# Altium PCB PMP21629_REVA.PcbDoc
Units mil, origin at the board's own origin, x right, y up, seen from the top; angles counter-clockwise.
Board outline 2050 x 1500 mil, 2 copper layers (Top Layer, Bottom Layer), stack 62 mil thick; 56 components, 27 nets, 156 pads, 15 vias.
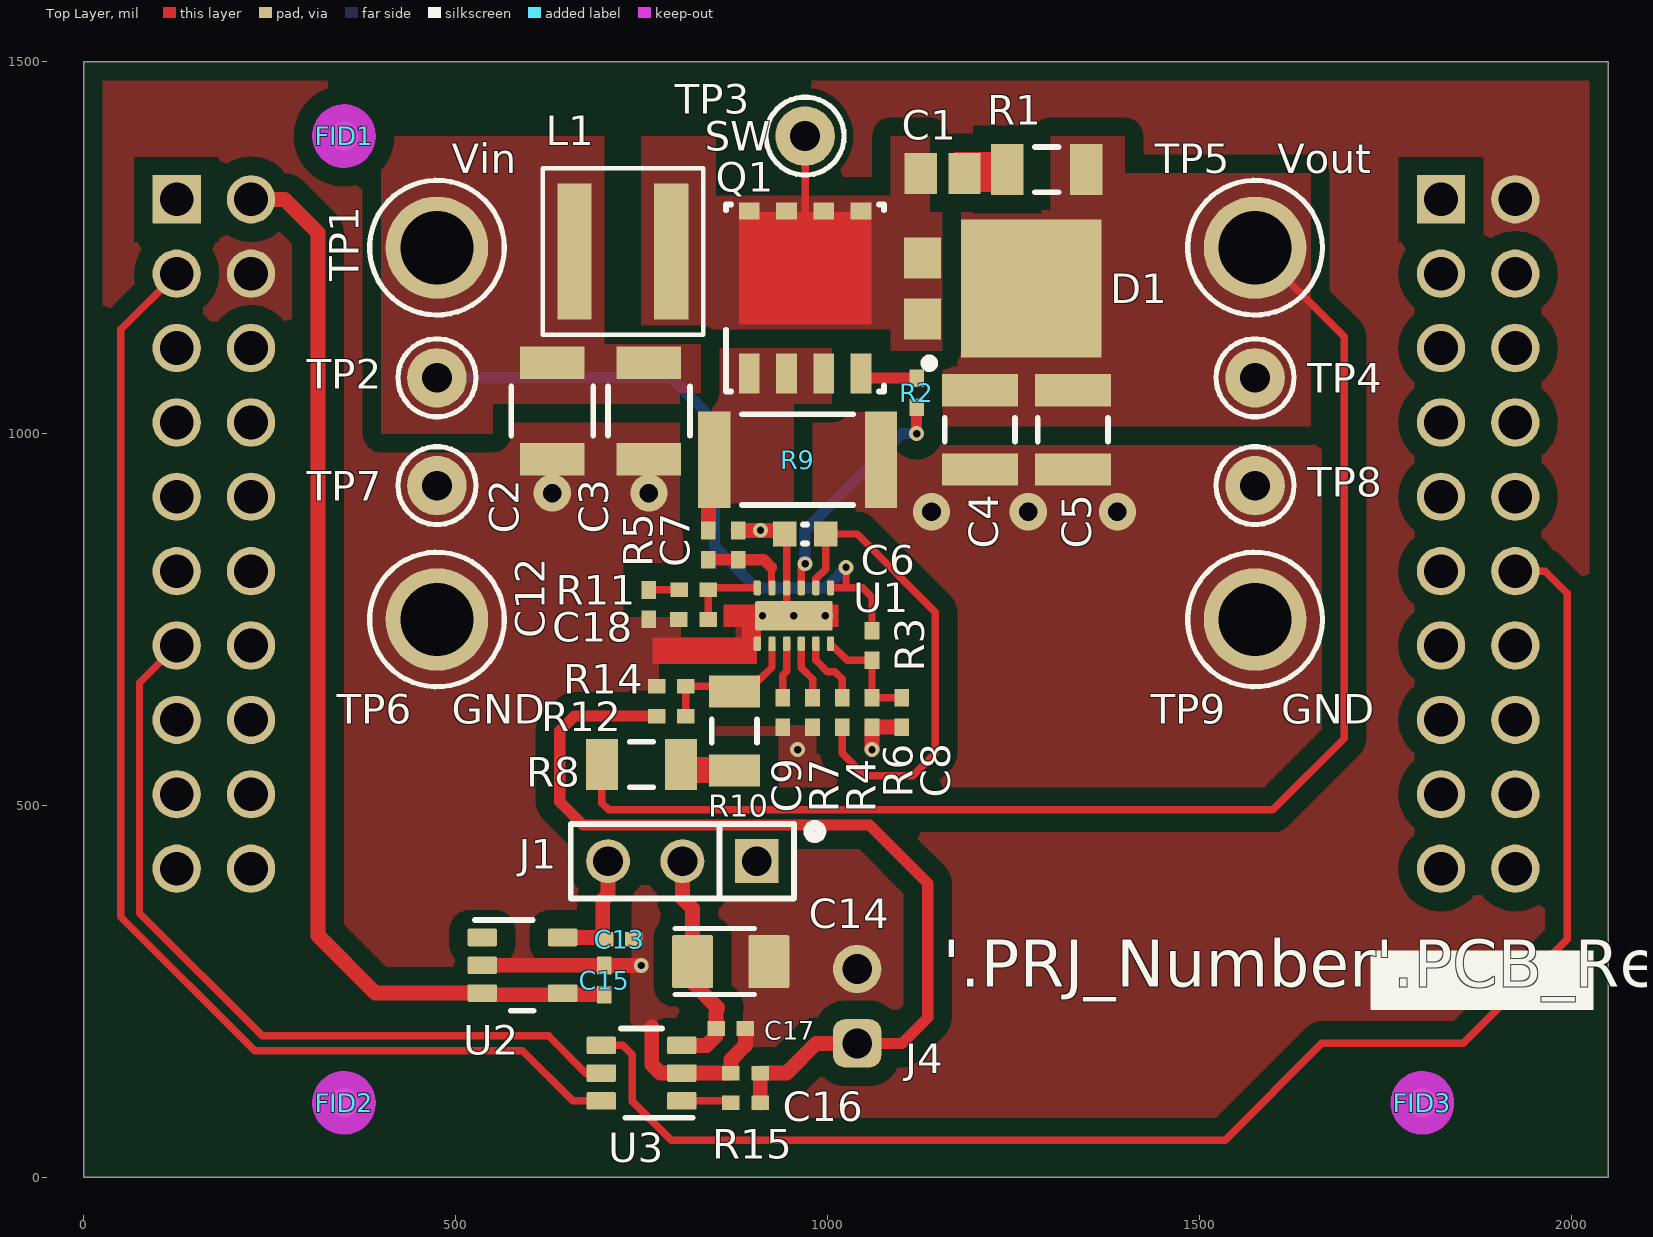
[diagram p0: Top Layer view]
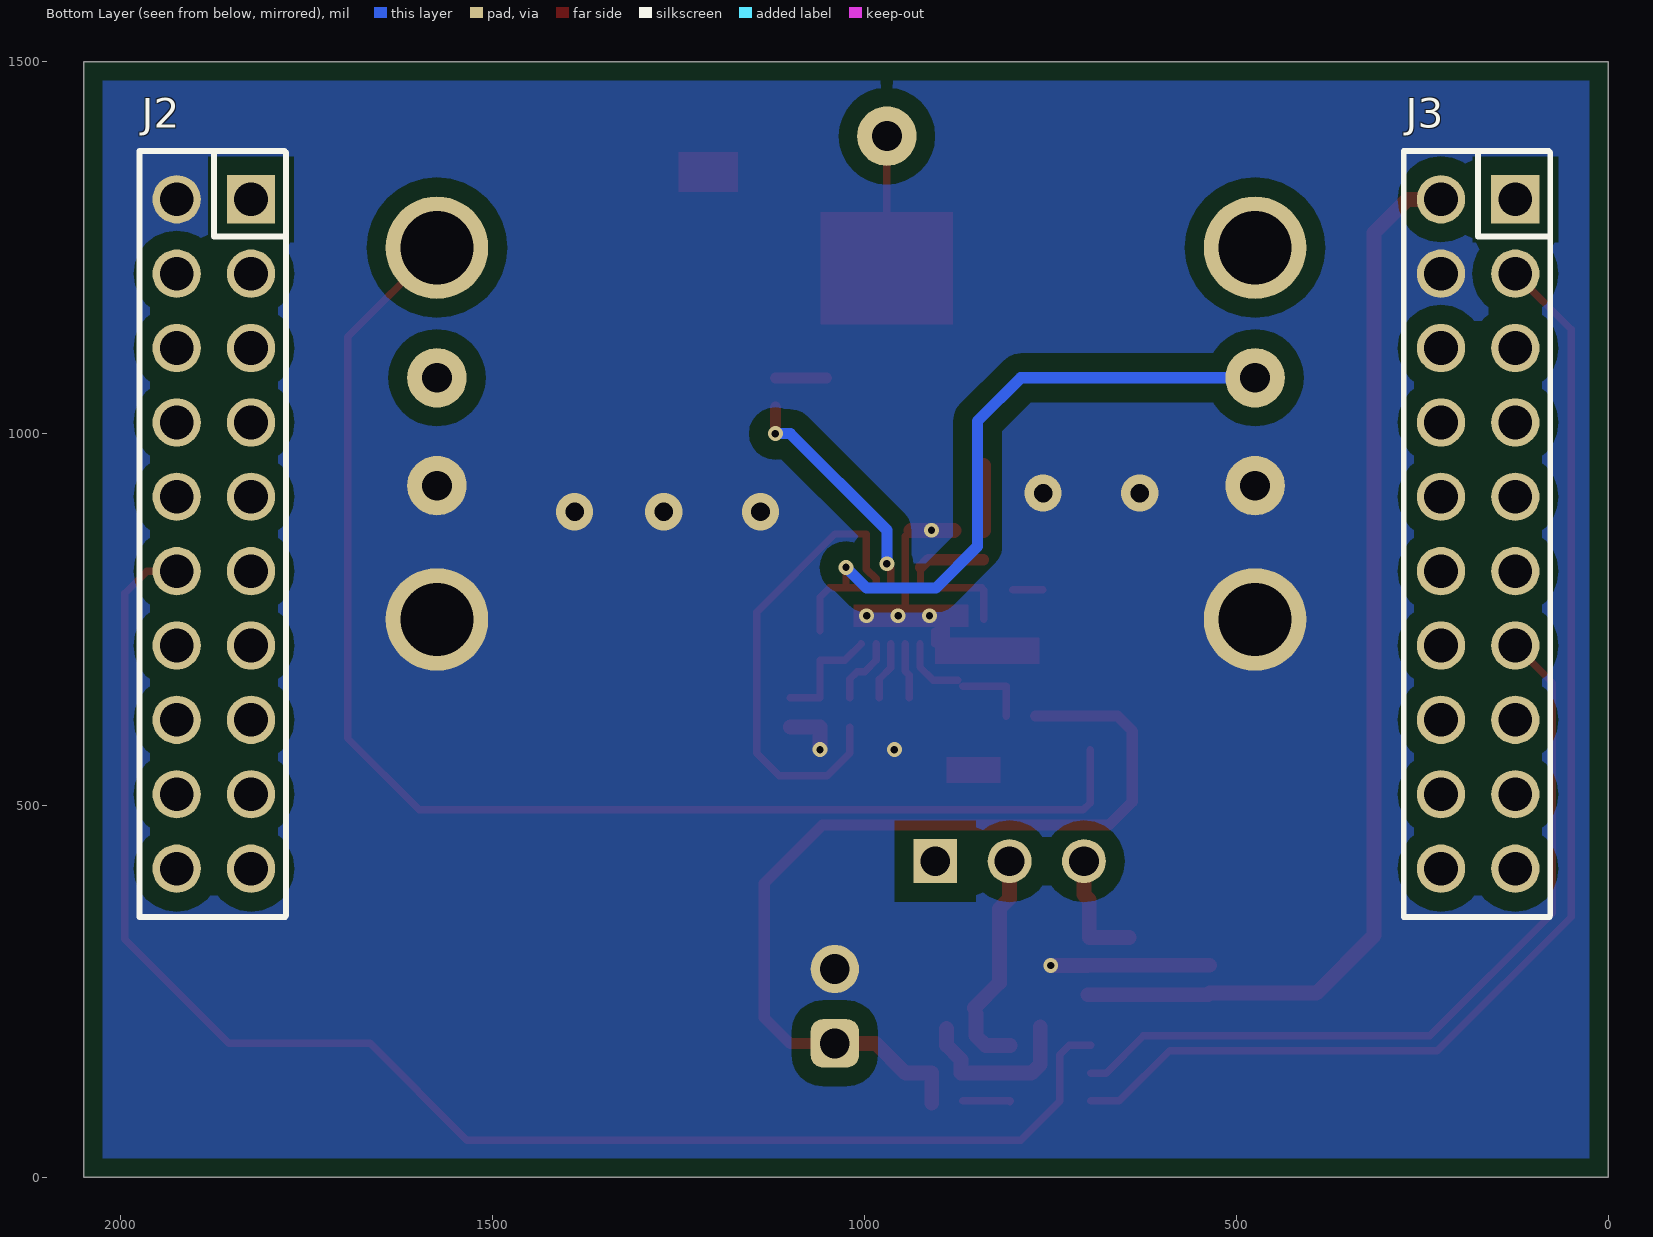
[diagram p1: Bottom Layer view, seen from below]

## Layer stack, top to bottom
Top Solder: solder mask 0.4, Solder Resist, Dk 3.5
Top Layer: signal copper 1.4
Dielectric1: core 59.2, FR-4, Dk 4.8
Bottom Layer: signal copper 1.4
Bottom Solder: solder mask 0.4, Solder Resist, Dk 3.5

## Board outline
0,0 2050,0 2050,1500 0,1500

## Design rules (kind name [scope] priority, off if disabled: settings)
AcuteAngle [All] p1: minimum=4.50000000000000E+0001 checktracksonly=FALSE
AssemblyTestPointUsage [All] p1: valid=2
BoardOutlineClearance BoardOutlineClearance_MountingHoles [OnCopper and InComponentClass('Mounting Holes')] p1: gap=40 ignorepadtopadclearanceinfootprint=FALSE
BoardOutlineClearance BoardOutlineClearance_Poly [OnCopper and IsPoly] p2: gap=25 ignorepadtopadclearanceinfootprint=FALSE
BoardOutlineClearance [OnCopper and Not InComponentClass('Logo') and not InComponentClass('FiducialMark') and not InRegion(1000,500,4000,800) and not InPoly] p3: gap=40 ignorepadtopadclearanceinfootprint=FALSE
Clearance Clearance_Keepouts [((IsTrack Or IsArc) And Not InPoly) And IsFree and IsKeepOut vs ((IsTrack Or IsArc) And Not InPoly) And IsFree and IsKeepOut] p1: gap=0 ignorepadtopadclearanceinfootprint=FALSE
Clearance Clearance_Poly [InPolygon] p2: gap=25 ignorepadtopadclearanceinfootprint=FALSE except(0: Arc-Hole Track-Hole SMDPad-Hole THPad-Hole Via-Hole Fill-Hole Poly-Hole Region-Hole Text-Hole)
Clearance Clearance_FiducialMark [IsKeepOut and InComponentClass('FiducialMark') vs IsPad and InComponentClass('FiducialMark')] p3: gap=0 ignorepadtopadclearanceinfootprint=FALSE
Clearance [All] p4: gap=7.87 ignorepadtopadclearanceinfootprint=FALSE except(0: Arc-Hole Track-Hole SMDPad-Hole THPad-Hole Via-Hole Fill-Hole Poly-Hole Region-Hole Text-Hole)
ComponentClearance ComponentClearance_MountingHoles_FiducialMarks [InComponentClass('Mounting Holes') vs InComponentClass('FiducialMark')] p1: gap=50 collisioncheckmode=3 verticalgap=10 showdistances=FALSE
ComponentClearance ComponentClearance_Shunt [InComponentClass('Header') vs InComponentClass('Shunt')] p2: gap=0 collisioncheckmode=3 verticalgap=0 showdistances=FALSE
ComponentClearance ComponentClearance_Logo [InComponentClass('Logo')] p3: gap=50 collisioncheckmode=3 verticalgap=10 showdistances=FALSE
ComponentClearance ComponentClearance_ScrewToNut [(HasFootprint('NY PMS 440 0025 PH')) vs (HasFootprint('Keystone_1902C'))] p4: gap=5 collisioncheckmode=3 verticalgap=10 showdistances=FALSE
ComponentClearance ComponentClearance_MountingHoles [InComponentClass('Mounting Holes')] p5: gap=250 collisioncheckmode=3 verticalgap=100000 showdistances=FALSE
ComponentClearance ComponentClearance_SmallPassives [HasFootprint('0201*') or HasFootprint('0402*') or HasFootprint('0508') or HasFootprint('0603*') or HasFootprint('0612') or HasFootprint('0805*') or HasFootprint('0815*') or HasFootprint('0830*') or HasFootprint('1206*') or HasFootprint('1210*') or HasFootprint('1808*') or HasFootprint('1812*') or HasFootprint('1825*') or HasFootprint('2010*') or HasFootprint('2220*') or HasFootprint('2225*') or HasFootprint('2512*') or HasFootprint('2728*') or HasFootprint('3518*') vs HasFootprint('0201*') or HasFootprint('0402*') or HasFootprint('0508') or HasFootprint('0603*') or HasFootprint('0612') or HasFootprint('0805*') or HasFootprint('0815*') or HasFootprint('0830*') or HasFootprint('1206*') or HasFootprint('1210*') or HasFootprint('1808*') or HasFootprint('1812*') or HasFootprint('1825*') or HasFootprint('2010*') or HasFootprint('2220*') or HasFootprint('2225*') or HasFootprint('2512*') or HasFootprint('2728*') or HasFootprint('3518*')] p6: gap=14.96 collisioncheckmode=3 verticalgap=10 showdistances=FALSE
ComponentClearance ComponentClearance_THtoSMT [IsThruComponent vs IsSMTComponent] p7: gap=40 collisioncheckmode=3 verticalgap=30 showdistances=FALSE
ComponentClearance ComponentClearance_THtoTH [IsThruComponent vs IsThruComponent] p8: gap=30 collisioncheckmode=3 verticalgap=30 showdistances=FALSE
ComponentClearance [All] p9: gap=30 collisioncheckmode=3 verticalgap=10 showdistances=FALSE
DiffPairsRouting [All] p1: maxlimit=100 minlimit=10 mostfreqgap=10 toplayer_minwidth=15 toplayer_maxwidth=15 toplayer_prefwidth=15 bottomlayer_minwidth=15 bottomlayer_maxwidth=15 bottomlayer_prefwidth=15 maxuncoupledlength=1000
FabricationTestPointUsage TestPointUsage [All] p1: valid=2 allowmultiple=FALSE
FabricationTestpoint Testpoint [All] p1: side=3 testpointundercomponent=TRUE minsize=40 maxsize=100 preferedsize=60 minholesize=0 maxholesize=40 preferedholesize=32 testpointgrid=1 allowsidetop=TRUE allowsidebottom=TRUE usegrid=TRUE gridtolerance=0.01
FanoutControl Fanout_LCC [IsLCC] p1: bgadir=Out bgaviamode=Centered fanoutstyle=Auto fanoutdirection=Alternating viagrid=1 // Fanout_LCC (Default Rule)
FanoutControl Fanout_BGA [IsBGA] p2: bgadir=Out bgaviamode=Centered fanoutstyle=Auto fanoutdirection=Alternating viagrid=1 // Fanout_BGA (Default Rule)
FanoutControl Fanout_Default [All] p4: bgadir=Out bgaviamode=Centered fanoutstyle=Auto fanoutdirection=Alternating viagrid=1 // Fanout_Default (Default Rule)
FanoutControl Fanout_Small [(CompPinCount < 5)] p5: bgadir=Out bgaviamode=Centered fanoutstyle=Auto fanoutdirection=OutThenIn viagrid=1 // Fanout_Small (Default Rule)
HoleSize [All] p1: absolutevalues=TRUE maxlimit=251 minlimit=7.87 maxpercent=80.000 minpercent=20.000
MinimumAnnularRing MinimumAnnularRing_ThermalPadVias [IsVia and InAnyComponent] p1: minimumring=5.91
MinimumAnnularRing [All] p2: minimumring=8
MinimumSolderMaskSliver MinimumSolderMaskSliver_Logo [InComponentClass('Logo') vs InComponentClass('Logo')] p1: minsoldermaskwidth=0.7
MinimumSolderMaskSliver [All] p2: minsoldermaskwidth=3.94
PlaneConnect [All] p1: planeconnectstyle=Direct reliefexpansion=10 reliefentries=4 reliefconductorwidth=10 reliefairgap=10
PolygonConnect [All] p1: connectstyle=Direct reliefconductorwidth=10 reliefentries=4 polygonreliefangle="90 Angle" airgapwidth=10
RoutingVias ThermalPadVias [IsVia and InAnyComponent] p1: holewidth=7.87 width=19.68 viastyle="Through Hole" minholewidth=7.87 minwidth=19.68 maxholewidth=12.99 maxwidth=23.62
RoutingVias [All] p2: holewidth=16 width=34 viastyle="Through Hole" minholewidth=7.87 minwidth=26 maxholewidth=40 maxwidth=65
SilkToBoardRegionClearance [Not ((IsComment or IsDesignator) And (Hide <> 'False')) and not InRegion(1000,500,4000,800)] p1:
SilkToSilkClearance SilkToSilkClearance_Pb-FreeLogo [(HasFootprint('Pb-Free_Overlay_Medium') OR HasFootprint('Pb-Free_Overlay_Small')) vs (HasFootprint('Pb-Free_Overlay_Medium') OR HasFootprint('Pb-Free_Overlay_Small'))] p1: silktosilkclearance=0
SilkToSilkClearance [All] p2: silktosilkclearance=4
SilkToSolderMaskClearance SilkToComponentPadClearance [(IsPad or IsFill or IsRegion) and InAnycomponent] p1: minsilkscreentomaskgap=5 clearancetoexposedcopper=TRUE
SilkToSolderMaskClearance "Silk to Solder Mask Opening" [All] p2: minsilkscreentomaskgap=4 clearancetoexposedcopper=FALSE
SolderMaskExpansion [All] p1: expansion=1.97
Width [All] p1: maxlimit=100 minlimit=6 preferedwidth=10 checkconnectedcopper=TRUE
15 further rules are at their usual default settings.

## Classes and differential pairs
component class AssemblyNote: ZZ1 ZZ2 ZZ3 ZZ4
component class FiducialMark: FID1 FID2 FID3
component class PMP21629_REVA_Hardware: FID1 FID2 FID3 ZZ1 ZZ2 ZZ3 ZZ4
component class Header: J1 J4
component class PMP21629_REVA: C1 C2 C3 C4 C5 C6 C7 C8 C9 C12 C13 C14 C15 C16 C17 C18 D1 J1 J2 J3 J4 L1 Q1 R1 R2 R3 R4 R5 R6 R7 R8 R9 R10 R11 R12 R14 R15 TP1 TP2 TP3 TP4 TP5 TP6 TP7 TP8 TP9 U1 U2 U3

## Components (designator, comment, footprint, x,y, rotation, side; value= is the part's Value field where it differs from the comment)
C1 "DNP" 0805L 1155,1350 r180 top value=470pF
C2 "C3225X7R1H106M250AC" 1210_280 630,1030.32 r270 top value=10uF
C3 "C3225X7R1H106M250AC" 1210_280 760,1030.32 r270 top value=10uF
C4 "CGA6N3X7R2A225K230AB" 1210_250L 1205,1005 r270 top value=2.2uF
C5 "CGA6N3X7R2A225K230AB" 1210_250L 1330,1005 r270 top value=2.2uF
C6 "CGA3E1X7R1C105K080AC" 0603L 970,865 r180 top value=1uF
C7 "GCM155R71H102KA37D" 0402L 880,850 r90 top value=1000pF
C8 "GRM1555C1H221JA01D" 0402L 1100,625 r270 top value=220pF
C9 "GRM155R61C474KE01" 0402L 940,625 r270 top value=0.47uF
C12 "GRM155R71E473KA88D" 0402L 760,770 r270 top value=0.047uF
C13 "GRM155R71E473KA88D" 0402L 720,320 r0 top value=0.047uF
C14 "TPSA106K010R0900" 3216-18 870,290 r0 top value=10uF
C15 "C0402C104K4RACAUTO" 0402L 700,265 r90 top value=0.1uF
C16 "GCM155R71E103KA37D" 0402L 890,140 r180 top value=0.01uF
C17 "CGA2B3X7R1H104M050BB" 0402L 870,200 r180 top value=0.1uF
C18 "DNP" 0402L 820,750 r180 top value=1000pF
D1 "FSV10150V" TO-277A 1200,1195 r90 top value=150V
FID1 "Fiducial" Fiducial10-20 350,1400 r0 top
FID2 "Fiducial" Fiducial10-20 350,100 r0 top
FID3 "Fiducial" Fiducial10-20 1800,100 r0 top
J1 "PEC03SAAN" CONN_PEC03SAAN 805,425 r180 top
J2 "DNP" CONN_SSW-110-23-F-D 1875,865 r90 bottom
J3 "DNP" CONN_SSW-110-23-F-D 175,865 r90 bottom
J4 "TSW-102-07-G-S" TSW-102-07-G-S 1040,230 r90 top
L1 "XAL5030-601MEB" XAL5030 725,1245 r0 top value=600nH
Q1 "FDMS86255" TRANS_NexFET_Q5B 970,1190 r90 top value=150V
R1 "DNP" 1206L 1295,1355 r0 top value=4.99
R2 "CRCW04020000Z0ED" 0402L 1120,1055 r90 top value=0
R3 "CRCW0402162KFKED" 0402L 1060,715 r90 top value=162k
R4 "CRCW040210K0JNED" 0402L 1020,625 r90 top value=10k
R5 "CRCW0402100RJNED" 0402L 840,850 r90 top value=100
R6 "CRCW040260K4FKED" 0402L 1060,625 r90 top value=60.4k
R7 "CRCW040249K9FKED" 0402L 980,625 r90 top value=49.9k
R8 "RC1206FR-0749R9L" 1206L 750,555 r180 top value=49.9
R9 "PMR100HZPFU5L00" 2512L 960,965 r180 top value=0.005
R10 "CRCW120680K6FKEA" 1206L 875,600 r270 top value=80.6k
R11 "CRCW04022K49FKED" 0402L 820.32,790 r0 top value=2.49k
R12 "CRCW04026K49FKED" 0402L 790,620 r180 top value=6.49k
R14 "CRCW04021K13FKED" 0402L 790,660 r0 top value=1.13k
R15 "CRCW0402200RFKED" 0402L 890,100 r0 top value=200
TP1 "Vin" Keystone1502-2 475,1250 r0 top
TP2 "Vin" Keystone5000 475,1075 r90 top
TP3 "SW" Keystone5002 970,1400 r90 top
TP4 "Vout" Keystone5000 1575,1075 r90 top
TP5 "Vout" Keystone1502-2 1575,1250 r0 top
TP6 "GND" Keystone1502-2 475,750 r0 top
TP7 "GND" Keystone5001 475,930 r90 top
TP8 "GND" Keystone5001 1575,930 r90 top
TP9 "GND" Keystone1502-2 1575,750 r0 top
U1 "LM51551QDSSRQ1" DSS0012C 955,755 r270 top
U2 "LM4120IM5-4.1/NOPB" DBV0005A_N 590,285 r0 top
U3 "DAC121S101QCMK/NOPB" DDC0006A_N 750,140 r180 top
ZZ1 "This Assembly Note is for PCB labels only" AssemblyNoteLabel 185,3938 r0 top
ZZ2 "This Assembly Note will show in the PcbDoc and associated outputs" AssemblyNote 185,3829.11 r0 top
ZZ3 "This Assembly Note will show in the PcbDoc and associated outputs" AssemblyNote 185,3740.56 r0 top
ZZ4 "This Assembly Note will show in the PcbDoc and associated outputs" AssemblyNote 185,3652 r0 top

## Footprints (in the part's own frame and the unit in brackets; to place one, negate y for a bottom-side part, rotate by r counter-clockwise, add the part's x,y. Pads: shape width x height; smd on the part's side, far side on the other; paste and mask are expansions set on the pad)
0402L [mm] "0402 from SM-752 data"
  rect 0.6x0.5 smd: 1(-0.5,0) 2(0.5,0)
  body extent -0.55,-0.3 0.55,0.3, height 0.6
0603L [mm] "0603 from SM-752 data"
  rect 0.8x0.85 smd: 1(-0.7,0) 2(0.7,0)
  silkscreen extent -0.07,-0.33 0.07,0.33, body extent -0.87,-0.47 0.87,0.47, height 1
0805L [mm] "0805 from SM-752 data"
  rect 1.1x1.4 smd: 1(-0.75,0) 2(0.75,0)
  body extent -1.1,-0.72 1.1,0.72, height 1.45
1206L [mm] "1206 from SM-752 data"
  rect 1.1x1.75 smd: 1(-1.35,0) 2(1.35,0)
  silkscreen extent -0.4,-0.77 0.4,0.77, body extent -1.7,-0.9 1.7,0.9, height 1.35
1210_250L [mm] "1210"
  rect 1.1x2.6 smd: 1(-1.35,0) 2(1.35,0)
  silkscreen extent -0.4,-1.2 0.4,1.2, body extent -1.7,-1.35 1.7,1.35, height 2.5
1210_280 [mm] "SMD, 2-Leads, Body 3.6x2.8mm, Height 2.8mm"
  rect 1.1x2.2 smd: 1(-1.65,0) 2(1.65,0)
  silkscreen extent -0.84,-1.4 0.84,1.4, body extent -1.8,-1.4 1.8,1.4, height 2.8
2512L [mm] "Chip Resistor, Body 6.3x3.2mm, IPC High Density"
  rect 1.1x3.3 smd: 1(-2.85,0) 2(2.85,0)
  silkscreen extent -1.9,-1.55 1.9,1.55, body extent -3.22,-1.67 3.22,1.67, height 0.71
3216-18 [mm] "Based on AVX recommendation in http://www.avx.com/download/software/literature/AVX-Footprint-Library.pdf"
  rrect7% 1.4x1.8 smd: 1(-1.3,0) 2(1.3,0)
  silkscreen extent -1.9,-1.12 0.8,1.12, body extent -1.7,-0.9 1.7,0.9, height 1.82
AssemblyNote [mil] "Assembly Note"
AssemblyNoteLabel [mil] "Assembly Note for PCB Labels"
CONN_PEC03SAAN [mm] "SULLINS"
  rect 1.5x1.5 hole 1.016: 1(-2.54,0)
  round 1.5 hole 1.016: 2(0,0) 3(2.54,0)
  silkscreen extent -4.72,-1.27 3.81,1.27, body extent -3.84,-1.3 3.84,1.3, height 8.38
CONN_SSW-110-23-F-D [mm] "SAMTEC"
  rect 1.65x1.65 hole 1.15: 1(11.43,-1.27)
  round 1.65 hole 1.15: 2(11.43,1.27) 3(8.89,-1.27) 4(8.89,1.27) 5(6.35,-1.27) 6(6.35,1.27) 7(3.81,-1.27) 8(3.81,1.27) 9(1.27,-1.27) 10(1.27,1.27) 11(-1.27,-1.27) 12(-1.27,1.27) 13(-3.81,-1.27) 14(-3.81,1.27) 15(-6.35,-1.27) 16(-6.35,1.27) 17(-8.89,-1.27) 18(-8.89,1.27) 19(-11.43,-1.27) 20(-11.43,1.27)
  silkscreen extent -13.08,-2.46 13.08,2.54, body extent -13,-2.51 13,2.54, height 8.59
DBV0005A_N [mm] "SOT23, 5-Leads, Body 2.9x1.6mm, Pitch 0.95mm, Lead Span 2.8mm, IPC Medium Density"
  rrect17% 1x0.6 smd: 1(-1.375,0.95) 2(-1.375,0) 3(-1.375,-0.95) 4(1.375,-0.95) 5(1.375,0.95)
  silkscreen extent -1.63,-1.55 0.38,1.55, body extent -1.42,-1.46 1.42,1.46, height 1.09
DDC0006A_N [mm]
  rrect17% 1x0.6 smd: 1(-1.375,0.95) 2(-1.375,0) 3(-1.375,-0.95) 4(1.375,-0.95) 5(1.375,0) 6(1.375,0.95)
  silkscreen extent -1.75,-1.52 0.7,1.53, body extent -1.43,-1.48 1.43,1.49, height 0.92
DSS0012C [mm] "WSON-12"
  rrect40% 0.5x0.25 smd: 1(-0.95,1.25) 2(-0.95,0.75) 3(-0.95,0.25) 4(-0.95,-0.25) 5(-0.95,-0.75) 6(-0.95,-1.25) 7(0.95,-1.25) 8(0.95,-0.75) 9(0.95,-0.25) 10(0.95,0.25) 11(0.95,0.75) 12(0.95,1.25)
  rrect11% 0.95x1.17 on Top Paste: 13(0,0.685) 13(0,-0.685)
  rrect11% 1x2.65 smd paste-0.5: 13(0,0)
  body extent -1,-1.5 1,1.5, height 0.81
Fiducial10-20 [mm]
  round 1 smd mask+0.5: 1(0,0)
  Top Layer keep-out circle w1.178: c0,0 r0.5
Keystone1502-2 [mm] "Double Turret"
  round 3.5 hole 2.5: 1(0,0)
  silkscreen extent -2.3,-2.3 2.3,2.3, body extent -1.6,-1.6 1.59,1.6, height 5.62
Keystone5000 [mil] "For Keystone 500x miniature loop terminals"
  round 80 hole 40: 1(0,0)
  silkscreen extent -52,-52 52,52, body extent -49,-49 49,49, height 182
Keystone5001 [mil] "For Keystone 500x miniature loop terminals"
  round 80 hole 40: 1(0,0)
  silkscreen extent -52,-52 52,52, body extent -49,-49 49,49, height 182
Keystone5002 [mil] "For Keystone 500x miniature loop terminals"
  round 80 hole 40: 1(0,0)
  silkscreen extent -52,-52 52,52, body extent -49,-49 49,49, height 182
TO-277A [mm] "Vishay"
  rect 1.4x1.27 smd: 1(-1.04,1.83) 2(1.04,1.83)
  rect 4.72x4.8 smd: 3(0,-1.883)
  silkscreen extent -2.7,1.45 -2.4,1.75, body extent -2.35,-4.2 2.4,2.45, height 1.2
TRANS_NexFET_Q5B [mm] "TI recommended land pattern (nominal) November 2012"
  rect 1.372x0.71 smd paste-0.4: 1(-2.776,1.905) 2(-2.776,0.635) 3(-2.776,-0.635) 4(-2.776,-1.905)
  rect 0.59x0.71 smd paste-0.3: 5(2.776,-1.905) 6(2.776,-0.635) 7(2.776,0.635) 8(2.776,1.905)
  Top Layer region: -1.106,-2.26 2.744,-2.26 2.744,2.26 -1.106,2.26
  silkscreen extent -3.38,-2.7 3,2.7, body extent -3.23,-2.55 2.87,2.55, height 1.06
TSW-102-07-G-S [mm] "Samtec 100mil, 1x2, 230 mil above insulator"
  rrect50% 1.65x1.65 hole 1.016: 1(-1.27,0)
  round 1.65 hole 1.016: 2(1.27,0)
  body extent -2.54,-1.27 2.54,1.27, height 8.38
XAL5030 [mil] "Coilcraft XAL5030 12/12/11"
  rect 46x183 smd: 1(-65,0) 2(65,0)
  silkscreen extent -108,-112 108,112, body extent -108,-112 108,112, height 122

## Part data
C1: library part CMP-0008122-2, "CAP, CERM, 470 pF, 100 V, +/- 5%, C0G/NP0, 0805", Cap_Case=0805, Manufacturer=MuRata, PartNumber=GRM2165C2A471JA01D, Supplier Part Number 1=490-1611-1-ND, TempCo=C0G/NP0, Tolerance_%=5%, Value1=Unknown, Value2=100V, ValueDisplayed=470pF
C2 C3: library part CMP-0009120-1, "CAP, CERM, 10 uF, 50 V, +/- 20%, X7R, 1210", Cap_Case=1210, Manufacturer=TDK, Supplier Part Number 1=445-14933-1-ND, TempCo=X7R, Tolerance_%=20%, Value1=Unknown, Value2=50V, ValueDisplayed=10uF
C4 C5: library part CMP-0009152-2, "CAP, CERM, 2.2 uF, 100 V, +/- 10%, X7R, AEC-Q200 Grade 1,", Cap_Case=1210_250, Manufacturer=TDK, Supplier Part Number 1=445-5866-1-ND, TempCo=X7R, Tolerance_%=10%, Value1="0.00173 ohm", Value2=100V, ValueDisplayed=2.2uF
C6: library part CMP-0079607-1, "CAP, CERM, 1 µF, 16 V,+/- 10%, X7R, AEC-Q200 Grade 1, 0603", Cap_Case=0603, Manufacturer=TDK, Supplier Part Number 1=445-12539-1-ND, TempCo=X7R, Tolerance_%=10%, Value2=16V, ValueDisplayed=1µF
C7: library part CMP-0006354-2, "CAP, CERM, 1000 pF, 50 V, +/- 10%, X7R, AEC-Q200 Grade 1, 0402", Cap_Case=0402, Manufacturer=MuRata, Supplier Part Number 1=490-4761-1-ND, TempCo=X7R, Tolerance_%=10%, Value1=Unknown, Value2=50V, ValueDisplayed=1000pF
C8: library part CMP-0006440-2, "CAP, CERM, 220 pF, 50 V, +/- 5%, C0G/NP0, 0402", Cap_Case=0402, Manufacturer=MuRata, Supplier Part Number 1=490-1293-1-ND, TempCo=C0G/NP0, Tolerance_%=5%, Value1=Unknown, Value2=50V, ValueDisplayed=220pF
C9: library part CMP-0006600-2, "CAP, CERM, 0.47 uF, 16 V, +/- 10%, X5R, 0402", Cap_Case=0402, Manufacturer=MuRata, TempCo=X5R, Tolerance_%=10%, Value1=Unknown, Value2=16V, ValueDisplayed=0.47uF
C12 C13: library part CMP-0006669-2, "CAP, CERM, 0.047 uF, 25 V, +/- 10%, X7R, 0402", Cap_Case=0402, Manufacturer=MuRata, Supplier Part Number 1=490-3254-1-ND, TempCo=X7R, Tolerance_%=10%, Value1=Unknown, Value2=25V, ValueDisplayed=0.047uF
C14: library part CMP-0011484-2, "CAP, TA, 10 uF, 10 V, +/- 10%, 0.9 ohm, SMD", Cap_Case=A, Manufacturer=AVX, Supplier Part Number 1=478-1751-1-ND, Tolerance_%=10%, Value1="0.9 ohm", Value2=10V, ValueDisplayed=10uF
C15: library part CMP-0006237-2, "CAP, CERM, 0.1 uF, 16 V, +/- 10%, X7R, AEC-Q200 Grade 1, 0402", Cap_Case=0402, Manufacturer=Kemet, Supplier Part Number 1=399-6828-1-ND, TempCo=X7R, Tolerance_%=10%, Value1=Unknown, Value2=16V, ValueDisplayed=0.1uF
C16: library part CMP-0006352-2, "CAP, CERM, 0.01 uF, 25 V, +/- 10%, X7R, 0402", Cap_Case=0402, Manufacturer=MuRata, Supplier Part Number 1=490-6043-2-ND, TempCo=X7R, Tolerance_%=10%, Value1=Unknown, Value2=25V, ValueDisplayed=0.01uF
C17: library part CMP-0006326-2, "CAP, CERM, 0.1 uF, 50 V, +/- 20%, X7R, AEC-Q200 Grade 1, 0402", Cap_Case=0402, Manufacturer=TDK, Supplier Part Number 1=445-12271-1-ND, TempCo=X7R, Tolerance_%=20%, Value1=Unknown, Value2=50V, ValueDisplayed=0.1uF
C18: library part CMP-0006354-2, "CAP, CERM, 1000 pF, 50 V, +/- 10%, X7R, AEC-Q200 Grade 1, 0402", Cap_Case=0402, Manufacturer=MuRata, PartNumber=GCM155R71H102KA37D, Supplier Part Number 1=490-4761-1-ND, TempCo=X7R, Tolerance_%=10%, Value1=Unknown, Value2=50V, ValueDisplayed=1000pF
D1: library part CMP-0028890-1, "Diode, Schottky, 150 V, 10 A, AEC-Q101, TO-277A", Manufacturer="Fairchild Semiconductor", Supplier Part Number 1=FSV10150VCT-ND, Value1=10A, Value2=0.84V
FID1 FID2 FID3: "Fiducial mark.  There is nothing to buy or mount.", Manufacturer=N/A
J1: library part CMP-0002338-1, "Header, 100mil, 3x1, Tin, TH", Color=Black, Current_A=3A, Manufacturer="Sullins Connector Solutions", Supplier Part Number 1=S1012E-03-ND, Voltage_V=1.8kV
J2 J3: library part CMP-0075442-1, "Connector, Receptacle, 100mil, 10x2, Gold plated, TH", Manufacturer=Samtec, PartNumber=SSW-110-23-F-D
J4: library part CMP-0075405-2, "Header, 100mil, 2x1, Gold, TH", Color=Black, Current_A=6.3A, Manufacturer=Samtec, Supplier Part Number 1=SAM1029-02-ND, Voltage_V=550V
L1: library part CMP-0061005-2, "Inductor, Shielded, Composite, 600 nH, 17.7 A, 0.00411 ohm, AEC-Q200 Grade 1, SMD", Manufacturer=Coilcraft, Value1="0.00411 ohm", Value2=17.7A, ValueDisplayed=600nH
Q1: library part CMP-0001059-1, "MOSFET, N-CH, 150 V, 10 A, SON 5x6mm", Alternate Manufacturer=None, Manufacturer="Fairchild Semiconductor", Supplier Part Number 1=FDMS86255TR-ND, Value2="45 nC"
R1: library part CMP-0017049-3, "RES, 4.99, 1%, 0.25 W, AEC-Q200 Grade 0, 1206", Manufacturer=Vishay-Dale, PartNumber=CRCW12064R99FKEA, Power_W=250mW, Supplier Part Number 1=541-4.99FFCT-ND, TempCo="100 ppm/C", Tolerance_%=1%, Value2=0.25W, Value_Code=4R99, ValueDisplayed=4.99
R2: library part CMP-0026822-3, "RES, 0, 5%, 0.063 W, AEC-Q200 Grade 0, 0402", Manufacturer=Vishay-Dale, Power_W=63mW, Supplier Part Number 1=541-0.0JCT-ND, TempCo="200 ppm/C", Tolerance_%=5%, Value2=0.063W, Value_Code=0000, ValueDisplayed=0
R3: library part CMP-0026034-3, "RES, 162 k, 1%, 0.063 W, AEC-Q200 Grade 0, 0402", Manufacturer=Vishay-Dale, Power_W=63mW, Supplier Part Number 1=541-162KLCT-ND, TempCo="100 ppm/C", Tolerance_%=1%, Value2=0.063W, Value_Code=162k
R4: library part CMP-0026825-5, "RES, 10 k, 5%, 0.063 W, AEC-Q200 Grade 0, 0402", Manufacturer=Vishay-Dale, Power_W=63mW, Supplier Part Number 1=541-10KJCT-ND, TempCo="200 ppm/C", Tolerance_%=5%, Value2=0.063W, Value_Code=10k0, ValueDisplayed=10k
R5: library part CMP-0026824-3, "RES, 100, 5%, 0.063 W, AEC-Q200 Grade 0, 0402", Manufacturer=Vishay-Dale, Power_W=63mW, Supplier Part Number 1=541-100JCT-ND, TempCo="200 ppm/C", Tolerance_%=5%, Value2=0.063W, Value_Code=100R, ValueDisplayed=100
R6: library part CMP-0026486-2, "RES, 60.4 k, 1%, 0.063 W, AEC-Q200 Grade 0, 0402", Manufacturer=Vishay-Dale, Power_W=63mW, Supplier Part Number 1=541-60.4KLCT-ND, TempCo="100 ppm/C", Tolerance_%=1%, Value2=0.063W, Value_Code=60k4, ValueDisplayed=60.4k
R7: library part CMP-0026403-2, "RES, 49.9 k, 1%, 0.063 W, AEC-Q200 Grade 0, 0402", Manufacturer=Vishay-Dale, Power_W=63mW, Supplier Part Number 1=541-49.9KLCT-ND, TempCo="100 ppm/C", Tolerance_%=1%, Value2=0.063W, Value_Code=49k9, ValueDisplayed=49.9k
R8: library part CMP-0018328-2, "RES, 49.9, 1%, 0.25 W, 1206", Manufacturer="Yageo America", Power_W=250mW, Supplier Part Number 1=311-49.9FRCT-ND, TempCo="100 ppm/C", Tolerance_%=1%, Value2=0.25W, Value_Code=49R9, ValueDisplayed=49.9
R9: library part CMP-0015837-2, "RES, 0.005, 1%, 2 W, 2512", Manufacturer=Rohm, Power_W=2W, Supplier Part Number 1=RHM.005AUCT-ND, TempCo="100 ppm/C", Tolerance_%=1%, Value_Code=5L000, ValueDisplayed=0.005
R10: library part CMP-0017185-3, "RES, 80.6 k, 1%, 0.25 W, AEC-Q200 Grade 0, 1206", Manufacturer=Vishay-Dale, Power_W=250mW, Supplier Part Number 1=541-80.6KFCT-ND, TempCo="100 ppm/C", Tolerance_%=1%, Value2=0.25W, Value_Code=80k6, ValueDisplayed=80.6k
R11: library part CMP-0026237-2, "RES, 2.49 k, 1%, 0.063 W, AEC-Q200 Grade 0, 0402", Manufacturer=Vishay-Dale, Power_W=63mW, Supplier Part Number 1=541-2.49KLCT-ND, TempCo="100 ppm/C", Tolerance_%=1%, Value2=0.063W, Value_Code=2k49, ValueDisplayed=2.49k
R12: library part CMP-0026515-2, "RES, 6.49 k, 1%, 0.063 W, AEC-Q200 Grade 0, 0402", Manufacturer=Vishay-Dale, Power_W=63mW, Supplier Part Number 1=541-6.49KLCT-ND, TempCo="100 ppm/C", Tolerance_%=1%, Value2=0.063W, Value_Code=6k49, ValueDisplayed=6.49k
R14: library part CMP-0026076-3, "RES, 1.13 k, 1%, 0.063 W, AEC-Q200 Grade 0, 0402", Manufacturer=Vishay-Dale, Power_W=63mW, Supplier Part Number 1=541-1.13KLCT-ND, TempCo="100 ppm/C", Tolerance_%=1%, Value2=0.063W, Value_Code=1k13, ValueDisplayed=1.13k
R15: library part CMP-0026159-2, "RES, 200, 1%, 0.063 W, AEC-Q200 Grade 0, 0402", Manufacturer=Vishay-Dale, Power_W=63mW, Supplier Part Number 1=541-200LCT-ND, TempCo="100 ppm/C", Tolerance_%=1%, Value2=0.063W, Value_Code=200R, ValueDisplayed=200
TP1 TP5 TP6 TP9: library part CMP-0055113-1, "Terminal, Turret, TH, Double", Manufacturer=Keystone, PartNumber=1502-2, Supplier Part Number 1=36-1502-2-ND
TP2 TP4: library part CMP-0055137-1, "Test Point, Miniature, Red, TH", Color=Red, Manufacturer=Keystone, PartNumber=5000, Supplier Part Number 1=36-5000-ND
TP3: library part CMP-0055139-1, "Test Point, Miniature, White, TH", Color=White, Manufacturer=Keystone, PartNumber=5002, Supplier Part Number 1=36-5002-ND
TP7 TP8: library part CMP-0055138-1, "Test Point, Miniature, Black, TH", Color=Black, Manufacturer=Keystone, PartNumber=5001, Supplier Part Number 1=36-5001-ND
U1: library part CMP-0081541-1, "Automotive Grade 2.2-MHz Wide Input Non-synchronous Boost Controller, DSS0012C (WSON-12)", Alternate Manufacturer="Texas Instruments", Alternate PartNumber=LM51551QDSSTQ1
U2: library part CMP-0079364-1, "0.2% 50ppm/°C Drift Precision Series Voltage Reference with Shutdown Enable, DBV0005A (SOT-23-5)", Alternate Manufacturer="Texas Instruments", Alternate PartNumber=LM4120IM5X-4.1/NOPB
U3: library part CMP-0083725-1, "12-Bit Micro Power, RRO Digital-to-Analog Converter, DDC0006A (SOT-23-THIN-6)", Alternate Manufacturer="Texas Instruments", Alternate PartNumber=DAC121S101QCMKX/NOPB, Operating Temperature Range="-40 to 125 C", Rating=Automotive
ZZ1: library part AssemblyNoteLabel
ZZ2 ZZ3 ZZ4: library part AssemblyNote

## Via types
v1: diameter 20, hole 10, Top Layer to Bottom Layer, 10 vias
v2: diameter 50, hole 25, Top Layer to Bottom Layer, 5 vias

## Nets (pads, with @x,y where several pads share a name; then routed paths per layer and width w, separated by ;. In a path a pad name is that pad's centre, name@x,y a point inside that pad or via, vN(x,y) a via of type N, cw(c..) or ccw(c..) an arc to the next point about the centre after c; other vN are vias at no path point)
3V3: J3.1
5V: C15.1 J3.2 U2.3 U2.4 | length 1468.4
  Top Layer w20: J3.2 270,1315 315,1270 315,325 392.4,247.6 U2.3 ; U2.3@538.15,245.31 C15.1
COMP: C18.1 R11.2 U1.6 | length 103.1
  Top Layer w10: C18.1 R11.2@839.68,789.68 ; R11.2@842.4,792.4 U1.6
DACOUT: C16.1 J4.1 R12.2 R15.2 | length 1250.5
  Top Layer w15: R12.2 735,620 660,620 640,600 640,505 671.3,473.7 1056.3,473.7 1135,395 1135,215 1100,180 J4.1
  Top Layer w20: R15.2 C16.1 945,140 985,180 J4.1
FB: R10.1 R12.1 R14.2 U1.8 | length 188.1
  Top Layer w10: R12.1 R14.2 R10.1@868.15,660 ; R10.1@875,668.15 907.87,668.15 925.47,685.75 U1.8
GDRV: R2.1 U1.3 | length 318.9
  Top Layer w10: U1.3 964.84,819.84 v1(970,825)
  Top Layer w15: v1(1120,1000) R2.1
  Bottom Layer w15: v1(970,825) 970,870 1100,1000 v1(1120,1000)
GND: C2.2 C3.2 C4.2 C5.2 C6.2 C7.2 C8.2 C9.2 C12.2 C13.2 C14.2 C15.2 C16.2 C17.1 C18.2 J2.2 J3.4 J4.2 R6.1 R7.1 R9.1 R14.1 TP6.1 TP7.1 TP8.1 TP9.1 U1.4 U1.7 U1.13@955,755 U2.2 U3.2 | length 685.4
  Top Layer w10: U1.7 905.79,734.21 ; U1.13@945.16,764.84 U1.4 C6.2@945.16,862.28
  Top Layer w20: U2.2 C15.2@699.68,285 ; C15.2 v1(749.68,284.68) ; 763.8,202.04 763.8,151.67 775.47,140 U3.2 C16.2 870.31,158.03 889.68,177.4 C17.1 ; C7.2 C6.2@937.76,869.69 ; v1(1060,575) R6.1 C8.2
  other v1: 960,575 912.68,755 955,755 997.32,755 910,870
  other v2: 1140,895 1270,895 1390,895 630,920 760,920
ISNS: C7.1 R5.1 U1.5 | length 117.1
  Top Layer w10: 924.78,820.22 924.78,793.09 U1.5
  Top Layer w15: R5.1 C7.1 914.68,830.32 924.78,820.22
JA-2: J3.3 U3.6 | length 1644.4
  Top Layer w10: J3.3 50,1140 50,350 230,170 590,170 657.4,102.6 U3.6
JA-7: J3.13 U3.5 | length 1090.6
  Top Layer w10: J3.13 75,665 75,355 240,190 625,190 675,140 U3.5
JB-6: J2.12 U3.4 | length 2047.7
  Top Layer w10: U3.4 725,177.4 737.6,164.8 737.6,102.4 790,50 1535,50 1665,180 1855,180 1995,320 1995,785 1965,815 J2.12
NetC1_1: C1.1 R1.1
NetC12_1: C12.1 R11.1 | length 40.3
  Top Layer w10: C12.1@760.32,790 R11.1
NetC13_1: C13.1 J1.3 U2.5 | length 169.3
  Top Layer w20: U2.5 697.91,322.4 697.91,372.91 705,380 J1.3@705,435
NetQ1_1: Q1.1 Q1.2 Q1.3 R5.2 R9.2 | length 87.5
  Top Layer w20: R5.2 R9.2@840,957.2
NetQ1_4: Q1.4 R2.2 | length 69
  Top Layer w15: Q1.4@1051.01,1074.69 R2.2
NetR8_1: R8.1 R10.2
NetR15_1: R15.1 U3.1 | length 64.8
  Top Layer w10: U3.1@805,101.73 U3.1 R15.1@867.72,102.6
PGOOD: R4.2 U1.11 | length 93.5
  Top Layer w10: U1.11 984.53,695.47 1000,680 1010,680 1020,670 R4.2
RT: R7.2 U1.10 | length 79.2
  Top Layer w10: U1.10 964.84,685.16 980,670 R7.2
SS: C9.1 U1.9 | length 75
  Top Layer w10: C9.1 940,675 945.16,680.16 U1.9
SW: C1.2 D1.1 D1.2 L1.2 Q1.5 Q1.6 Q1.7 Q1.8 TP3.1 | length 120
  Top Layer w10: 970,1280 TP3.1
UVLO: C8.1 R3.1 R6.2 U1.12 | length 155.6
  Top Layer w10: U1.12 1026.5,695.32 R3.1 R6.2 C8.1
VA: C14.1 C17.2 J1.2 U3.3 | length 308.4
  Top Layer w20: U3.3 837.4,177.4 850.31,190.31 850.31,220 ; J1.2@805,435 805,375 818.82,361.18 818.82,300 818.82,261.34 852.6,227.56
VCC: C6.1 R4.1 U1.2 | length 644.1
  Top Layer w10: U1.2 984.53,804.53 997.56,817.57 C6.1 1040,865 1145,760 1145,570 1115,540 1050,540 1020,570 R4.1
Vin: C2.1 C3.1 L1.1 R3.2 TP1.1 TP2.1 U1.1 | length 911.4
  Top Layer w10: U1.1 1025.91,792.4 ; v1(1025,820) 1025,793.31 1025.91,792.4 ; R3.2 1060,780 1047.6,792.4 1025.91,792.4
  Bottom Layer w15: TP2.1 790,1075 848.03,1016.97 848.03,848.5 904.13,792.4 997.4,792.4 v1(1025,820)
Vout: C4.1 C5.1 D1.3 R1.2 R8.2 TP4.1 TP5.1 | length 1823.2
  Top Layer w10: R8.2@696.85,575 R8.2 696.85,503.15 705.93,494.07 1599.07,494.07 1695,590 1695,1130 TP5.1
pads on no net: FID1.1 FID2.1 FID3.1 J1.1 J2.1 J2.3 J2.4 J2.5 J2.6 J2.7 J2.8 J2.9 J2.10 J2.11 J2.13 J2.14 J2.15 J2.16 J2.17 J2.18 J2.19 J2.20 J3.5 J3.6 J3.7 J3.8 J3.9 J3.10 J3.11 J3.12 J3.14 J3.15 J3.16 J3.17 J3.18 J3.19 J3.20 U1.13@928.03,755 U1.13@981.97,755 U2.1

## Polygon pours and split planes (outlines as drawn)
GND on Top Layer "GND" (solid, remove dead copper, pour order 8): 0,1500 0,0 2050,0 2050,1500
Vout on Top Layer "Vout" (solid, remove dead copper, pour order 6): 1300,1400 1300,1300 1175,1300 1175,1090 1150,1090 1149.88,1010 1650,1010 1650,1350 1400,1350 1400,1400
NetQ1_1 on Top Layer "Q1" (solid, remove dead copper, pour order 4): 845,1120 845,900 955,900 955,1040 1015,1040 1015,1120
SW on Top Layer "SW" (solid, remove dead copper, pour order 2): 750,1400 750,1140 1085,1140 1085,1110 1085.35,1110.35 1160,1110.35 1160,1400 1085,1400 1085,1320 850,1320 850,1395 855,1400
Vin on Top Layer "Vin" (solid, remove dead copper, pour order 0): 400,1400 400,1000 550,1000 550,1040 835,1040 830,1045 830,1120 700,1120 700,1400
GND on Bottom Layer "GND" (solid, remove dead copper, pour order 10): 0,1500 0,0 2050,0 2050,1500

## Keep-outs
Keep-Out Layer:
  text ".Layer_Name" at 577,-858.49 h60

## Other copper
Top Layer:
  rectangle net GND: 765,690 905,725.47
  rectangle net GND: 885,700 905,740
  rectangle net GND: 860,740 1015,770
  rectangle net NetC1_1: 1170,1325 1250,1378.54
  rectangle net NetR8_1: 816.93,530 890.02,565
  text ".Layer_Name" at 577,-858.49 h60
Bottom Layer:
  text ".Layer_Name" at 577,-858.49 h60

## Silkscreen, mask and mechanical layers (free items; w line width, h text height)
Top Overlay:
  region: 2030,305 1730,305 1730,225 2030,225
  text "'.PRJ_Number'.PCB_Rev-" at 1155,235 h108.27
  text ".Layer_Name" at 577,-858.49 h60
Bottom Overlay:
  text ".Layer_Name" at 577,-858.49 h60
Top Paste:
  text ".Layer_Name" at 577,-858.49 h60
Bottom Paste:
  text ".Layer_Name" at 577,-858.49 h60
Top Solder:
  text ".Layer_Name" at 577,-858.49 h60
  text ".Layer_Name" at 577,-858.49 h60
Bottom Solder:
  text ".Layer_Name" at 577,-858.49 h60
Drill Guide:
  text ".Layer_Name" at 577,-858.49 h60
M1 Board Outline:
  the board outline again, w10
  text ".Layer_Name" at 577,-858.49 h60
M2 Board Dimensions:
  rectangle: 125,-400 500,-275
  rectangle: 0,-275 125,-150
  lines w7: 0,-275 1000,-275 ; 125,-400 125,-150 ; 250,-400 250,-150 ; 500,-400 500,-150 ; 750,-400 750,-150 ; 0,-400 0,-150 1000,-150 1000,-400 0,-400
  text ".Layer_Name" at 577,-858.49 h60
M3 3D STEP Top:
  text ".Layer_Name" at 577,-858.49 h60
M4 3D STEP Bottom:
  text ".Layer_Name" at 577,-858.49 h60
M5 Assembly Top:
  lines w10: -292,-930.17 6308,-930.17 ; -292,-726.83 6310,-726.83 ; -292,-523.5 -292,-1133.5 3713,-1133.5 6310,-1133.5 6310,-523.5 -291.5,-523.5 -291.5,-1133.5 1284,-1133.5 ; 2173,-1133.5 2173,-523.5 ; 3440,-726.83 3440,-523.5 ; 4280,-726.83 4280,-523.5 ; 4902,-1140 4902,-937.17
  text "COMPONENTS MARKED 'DNP' SHOULD NOT BE POPULATED." at 1153.5,-318.5 h60
  text "ASSEMBLY VARIANT:" at 1153,-434 h60
  text ".VariantName" at 2189,-434 h60
  text "PCB VIEWED FROM TOP SIDE" at -228.5,-655.67 h60
  text "BOARD #:" at 2248,-655.67 h60
  text ".PRJ_Number" at 2793.5,-655.67 h60
  text "REV:" at 3638,-655.67 h60
  text ".PCB_Rev" at 3929.5,-655.67 h60
  text "SVN REV:" at 4476,-655.67 h60
  text ".VersionControl_RevNumber" at 4982,-655.67 h60
  text "TID #:" at 2248,-859 h60
  text ".TID" at 2793.5,-859 h60
  text "PLOT NAME =" at -228.5,-1064.34 h60
  text ".plot_File_Name" at 577,-1064.34 h60
  text "GENERATED    :" at 2250,-1064.34 h60
  text ".Print_Date" at 3119.5,-1064.34 h60
  text ".Print_Time" at 3848.5,-1064.34 h60
  text "TEXAS INSTRUMENTS" at 5113,-1064.34 h60
M6 Assembly Bottom:
  lines w10: -292.5,-727.33 6309.5,-727.33 ; -290.5,-930.67 6309.5,-930.67 ; 1115.5,-1140.5 1115.5,-937.67 ; 1737.5,-727.33 1737.5,-524 ; 2577.5,-727.33 2577.5,-524 ; 3844.5,-1134 3844.5,-524 ; 4733.5,-1134 6309,-1134 6309,-524 -292.5,-524 -292.5,-1134 2304.5,-1134 6309.5,-1134 6309.5,-524
  text "COMPONENTS MARKED 'DNP' SHOULD NOT BE POPULATED." at 6102,-318 h60
  text ".VariantName" at 5058,-434 h60
  text "ASSEMBLY VARIANT:" at 6097,-434 h60
  text ".VersionControl_RevNumber" at 1035.5,-656.17 h60
  text "SVN REV:" at 1541.5,-656.17 h60
  text ".PCB_Rev" at 2088,-656.17 h60
  text "REV:" at 2379.5,-656.17 h60
  text ".PRJ_Number" at 3224,-656.17 h60
  text "BOARD #:" at 3769.5,-656.17 h60
  text "PCB VIEWED FROM BOTTOM SIDE" at 6246,-656.17 h60
  text ".TID" at 3224,-859.5 h60
  text "TID #:" at 3769.5,-859.5 h60
  text "TEXAS INSTRUMENTS" at 904.5,-1064.84 h60
  text ".Print_Time" at 2169,-1064.84 h60
  text ".Print_Date" at 2898,-1064.84 h60
  text "GENERATED    :" at 3767.5,-1064.84 h60
  text ".plot_File_Name" at 5440.5,-1064.84 h60
  text "PLOT NAME =" at 6246,-1064.84 h60
M9 Title Sheet:
  drawing of 57 lines, arcs and shapes, not listed
  text "1" at 739.84,8036.5 h70
  text "2" at 3235.5,8036.5 h70
  text "3" at 5724.84,8036.5 h70
  text "4" at 8231.51,8036.5 h70
  text "5" at 10730.5,8036.5 h70
  text "6" at 13235.5,8036.5 h70
  text "A" at -416.5,6893.5 h70
  text "A" at 14383.5,6893.5 h70
  text "B" at -416.5,4513.5 h70
  text "B" at 14383.5,4513.5 h70
  text "C" at -416.5,2138.5 h70
  text "C" at 14383.5,2138.5 h70
  text "PROJECT TITLE:" at 11343.5,277.5 h45
  text ".PRJ_Title" at 11393.5,144.17 h70
  text "DESIGNED FOR:" at 11343.5,-23.5 h45
  text ".PRJ_Customer" at 11393.5,-163.5 h70
  text "D" at -416.5,-231.5 h70
  text "D" at 14383.5,-231.5 h70
  text "FILE NAME:" at 11343.5,-323.5 h45
  text ".PCB_File_Name_No_Path" at 11393.5,-443.5 h70
  text "Texas Instruments (TI) and/or its licensors do not warrant the accuracy or completeness of this specification" at 6374,-605.34 h45
  text "ENGINEER:" at 11343.5,-613.5 h45
  text "LAYOUT BY:" at 12848.5,-613.5 h45
  text "or any information contained therein. TI and/or its licensors do not warrant that this design will meet" at 6329.01,-718 h45
  text ".PRJ_Engineer" at 11393.5,-768.49 h70
  text ".PCB_Layout" at 12899,-768.49 h70
  text "the specifications, will be suitable for your application or fit for any particular purpose, or will operate in" at 6329.01,-830.67 h45
  text ".Layer_Name" at 577,-858.49 h60
  text "ALTIUM DESIGNER VERSION:" at 12848.5,-923.5 h45
  text "an implementation. TI and/or its licensors do not warrant that the design is production worthy. You should" at 6329.01,-943.33 h45
  text "completely validate and test your design implementation to confirm the system functionality for your application." at 6374,-1056 h45
  text ".print_Scale" at 11393.5,-1056.83 h70
  text ".Application_BuildNumber" at 12899,-1056.83 h70
  text "1" at 739.84,-1263.5 h70
  text "2" at 3235.5,-1263.5 h70
  text "3" at 5724.84,-1263.5 h70
  text "4" at 8231.51,-1263.5 h70
  text "5" at 10730.5,-1263.5 h70
  text "6" at 13235.5,-1263.5 h70
M10 Fab Notes:
  drawing of 189 lines, arcs and shapes, not listed
  text "DESIGN INFORMATION" at 12382.02,6356.17 h60
  text "MIN. TRACK WIDTH:" at 11737.46,6224.05 h60
  text "8" at 12833.7,6224.05 h60
  text "MIL" at 12988.46,6224.05 h60
  text "MIN. CLEARANCE:" at 11737.46,6099.92 h60
  text "0.2" at 12773.7,6099.93 h60
  text "mm" at 12988.46,6099.92 h60
  text "MIN. VIA PAD SIZE:" at 11737.46,5975.8 h60
  text "24" at 12803.71,5975.8 h60
  text "MIL" at 12988.46,5975.8 h60
  text "0.05mm (2MIL)" at 12432.46,5845.9 h60
  text "MINIMUM ANNULAR RING" at 11408.23,5837.67 h60
  text "EXTERNAL" at 13140.46,5837.67 h60
  text "PER" at 11608.23,5727.55 h60
  text "IPC-D-275 CLASS 2 LEVEL C" at 11828.23,5727.54 h60
  text "MIL, HOLES" at 13316.46,5627.07 h60
  text "+/-" at 12924,5618.48 h60
  text "+/-" at 13778,5618.48 h60
  text "REGISTRATION TOLERANCES:" at 11408.23,5617.42 h60
  text "METAL" at 12608,5617.42 h60
  text "5" at 13184.2,5617.42 h60
  text "3" at 14017.2,5617.42 h60
  text "MIL" at 14133.46,5617.42 h60
  text "HOLE SIZE TOLERANCE (UNLESS OTHERWISE SPECIFIED):" at 11408.23,5519.1 h60
  text "+/-" at 13778,5516.23 h60
  text "3" at 14017.2,5515.17 h60
  text "MIL" at 14133.46,5515.17 h60
  text "MATERIAL:" at 11333.46,5377.52 h60
  text "FR-4 High Tg" at 12319.9,5249 h60
  text "X" at 12175.46,5241.01 h60
  text "FR-408" at 11754.46,5236.49 h60
  text "OTHER" at 13242.46,5236.49 h60
  text "62 MIL (1.6mm) +/-10%" at 12074.56,5093.46 h60
  text "X" at 11954.46,5091.01 h60
  text "THICKNESS:" at 11408.23,5085.24 h60
  text "OTHER" at 13359.46,5085.24 h60
  text "TOLERANCE:" at 11408.23,4946.92 h60
  text "X" at 12256.46,4946.92 h60
  text "ANSI IPC-6012 TYPE 3 CLASS 2" at 12434.48,4946.92 h60
  text "OTHER +/-" at 12434.46,4802.73 h60
  text "BOW & TWIST:" at 11408.23,4657.54 h60
  text "X" at 12256.46,4657.54 h60
  text "ANSI IPC-6012 TYPE 3 CLASS 2" at 12434.48,4657.54 h60
  text "OTHER +/-" at 12434.46,4510.85 h60
  text "DRILLING:" at 11333.46,4380.23 h60
  text "NC_DRILL FILES" at 13094.46,4275.04 h60
  text "REFERENCE:" at 11408.23,4271.1 h60
  text "X" at 12065.46,4271.01 h60
  text "AS SHOWN" at 12243.46,4271.1 h60
  text "X" at 12966.46,4271.1 h60
  text "OTHER" at 13392.46,4128.85 h60
  text "PTH COPPER THICKNESS:" at 11407.91,4125.32 h60
  text "X" at 12547.14,4125.32 h60
  text "20-30 um" at 12675.14,4125.32 h60
  text "BOARD FINISH:" at 11333.46,3977.73 h60
  text "SILKSCREEN:" at 11488.68,3867.6 h60
  text "X" at 12446.46,3867.6 h60
  text "TOP" at 12563.46,3867.6 h60
  text "X" at 12956.46,3867.6 h60
  text "BOTTOM" at 13074.46,3867.6 h60
  text "SILKSCREEN COLOR:" at 11488.68,3712.41 h60
  text "X" at 12445.46,3712.41 h60
  text "WHITE" at 12563.46,3712.41 h60
  text "OTHER" at 13074.46,3712.41 h60
  text "X" at 12576.46,3568.96 h60
  text "GREEN" at 12694.46,3568.96 h60
  text "OTHER" at 13312.46,3568.96 h60
  text "SOLDER RESIST COLOR:" at 11488.68,3562.1 h60
  text "X" at 12576.46,3414.71 h60
  text "MATTE" at 12694.46,3414.71 h60
  text "SEMI-GLOSS" at 13312,3414.07 h60
  text "IMMERSION GOLD (ENIG)" at 12394.46,3241.94 h60
  text "ENEPIG" at 13732,3234.72 h60
  text "SURFACE FINISH:" at 11333.46,3233.72 h60
  text "X" at 12216.46,3233.72 h60
  text "IMM. TIN/SILVER OR EQUIV" at 11663,3096.4 h60
  text "OTHER" at 13094.46,3092.47 h60
  text "ARRAY/PANEL:" at 11333.46,2937.09 h60
  text "CUT AND TRIM PER M1 BOARD OUTLINE" at 12394.46,2928.87 h60
  text "N.C. ROUTE" at 12394.46,2792.9 h60
  text "X" at 13082.46,2792.9 h60
  text "V. SCORE" at 13260.46,2792.9 h60
  text "CERTIFICATION:" at 11333.46,2663.77 h60
  text "MATERIALS AND WORKMANSHIP FOR ALL PCBS" at 12058.46,2663.77 h60
  text "TO MEET OR EXCEED THE REQUIREMENTS OF:" at 12058.46,2569.71 h60
  text "X" at 11695.97,2441.08 h60
  text "ANSI IPC-A-600F CLASS ->" at 11823.96,2441.08 h60
  text "X" at 13471.97,2441.08 h60
  text "2" at 13581.96,2441.08 h60
  text "1" at 13266.96,2439.58 h60
  text "3" at 13935.96,2439.58 h60
  text "X" at 12507.97,2293.39 h60
  text "RoHS" at 12635.96,2293.39 h60
  text "OTHER" at 13280.36,2293.39 h60
  text "PER ORDER" at 13677.42,2293.39 h60
  text "ALL BOARDS MUST MEET OR EXCEED UL94-V0 REQUIREMENTS." at 11361,2139.57 h60
  text "PCB MUST BEAR THE UL94V-0 UL REGISTERED MATERIAL ID NUMBER" at 11361,2023.5 h60
  text "ADDITIONAL REQUIREMENTS:" at 11333.46,1854.08 h60
  text "MICROSECTION:" at 11408.23,1746.95 h60
  text "YES" at 12313.96,1746.95 h60
  text "REQUIRED" at 13175.46,1602.62 h60
  text "BARE BOARD ELEC. TEST:" at 11408.23,1599.76 h60
  text "NONE" at 12713.96,1599.76 h60
  text "X" at 13057.46,1599.76 h60
  text "PER ORDER" at 13767.46,1599.76 h60
  text "XX MIL VIAS REQUIRE NON-CONDUCTIVE FILL AND PLANARIZE" at 11576.38,1394.82 h59
  text "XX MIL VIAS REQUIRE CONDUCTIVE FILL AND PLANARIZE" at 11584.38,1290.84 h60
  text "OUTER XX MIL VIAS REQUIRE 50 OHM SINGLE-ENDED IMPEDANCE" at 11583.39,1127.46 h58
  text "LAYER 2 & 3 (INNER LAYERS) XX MIL WIDE, XX MIL SPACE / TRACES REQUIRE 100 OHM DIFFERENTIAL IMPEDANCE" at 11575.39,891.74 h60
  text ".Layer_Name" at 577,-858.49 h60
M11 Gerber Information:
  lines w10: -292,-930.17 6308,-930.17 ; -292,-726.83 6310,-726.83 ; -292,-523.5 -292,-1133.5 3713,-1133.5 6310,-1133.5 6310,-523.5 -291.5,-523.5 -291.5,-1133.5 1284,-1133.5 ; 2173,-1133.5 2173,-523.5 ; 3440,-726.83 3440,-523.5 ; 4280,-726.83 4280,-523.5 ; 4902,-1140 4902,-937.17
  text "ALL ARTWORK VIEWED FROM TOP SIDE" at -228.5,-655.67 h60
  text "BOARD #:" at 2248,-655.67 h60
  text ".PRJ_Number" at 2793.5,-655.67 h60
  text "REV:" at 3638,-655.67 h60
  text ".PCB_Rev" at 3929.5,-655.67 h60
  text "SVN REV:" at 4476,-655.67 h60
  text ".VersionControl_RevNumber" at 4982,-655.67 h60
  text "LAYER NAME =" at -228.5,-858.49 h60
  text "TID #:" at 2248,-859 h60
  text ".TID" at 2793.5,-859 h60
  text "PLOT NAME =" at -228.5,-1064.34 h60
  text ".plot_File_Name" at 577,-1064.34 h60
  text "GENERATED    :" at 2250,-1064.34 h60
  text ".Print_Date" at 3119.5,-1064.34 h60
  text ".Print_Time" at 3848.5,-1064.34 h60
  text "TEXAS INSTRUMENTS" at 5113,-1064.34 h60
M12 Stackup:
  drawing of 191 lines, arcs and shapes, not listed
  text "Layer" at 9790.34,7830 h60
  text "Name" at 10200.26,7830 h60
  text "Material" at 11130,7830 h60
  text "Thickness" at 11989.77,7830 h60
  text "Constant" at 12639.6,7830 h60
  text "Board Layer Stack" at 13209.46,7830 h60
  text "1" at 9790.34,7710 h60
  text "Top Overlay" at 10200.26,7710 h60
  text "2" at 9790.34,7590 h60
  text "Top Solder" at 10200.26,7590 h60
  text "Solder Resist" at 11130,7590 h60
  text "0.40mil" at 11989.77,7590 h60
  text "3.5" at 12639.6,7590 h60
  text "3" at 9790.34,7470 h60
  text "Top Layer" at 10200.26,7470 h60
  text "Copper" at 11130,7470 h60
  text "1.40mil" at 11989.77,7470 h60
  text "4" at 9790.34,7350 h60
  text "Dielectric1" at 10200.26,7350 h60
  text "FR-4" at 11130,7350 h60
  text "59.20mil" at 11989.77,7350 h60
  text "4.8" at 12639.6,7350 h60
  text "5" at 9790.34,7230 h60
  text "Bottom Layer" at 10200.26,7230 h60
  text "Copper" at 11130,7230 h60
  text "1.40mil" at 11989.77,7230 h60
  text "6" at 9790.34,7110 h60
  text "Bottom Solder" at 10200.26,7110 h60
  text "Solder Resist" at 11130,7110 h60
  text "0.40mil" at 11989.77,7110 h60
  text "3.5" at 12639.6,7110 h60
  text "7" at 9790.34,6990 h60
  text "Bottom Overlay" at 10200.26,6990 h60
  text ".Layer_Name" at 577,-858.49 h60
M13 Component Bodies Top:
  text ".Layer_Name" at 577,-858.49 h60
M14 Component Bodies Bottom:
  text ".Layer_Name" at 577,-858.49 h60
M15 Courtyards Top:
  text ".Layer_Name" at 577,-858.49 h60
M16 Courtyards Bottom:
  text ".Layer_Name" at 577,-858.49 h60
Drill Drawing:
  circle w10: c5363.8,3266.08 r27.66
  lines w10: 5336.14,2740.59 5391.46,2740.59 5391.46,2795.9 5336.14,2795.9 5336.14,2740.59 ; 5336.14,2878.87 5349.97,2878.87 5363.8,2865.04 5377.63,2878.87 5391.46,2878.87 5377.63,2892.7 5391.46,2906.53 5377.63,2906.53 5363.8,2920.36 5349.97,2906.53 5336.14,2906.53 5349.97,2892.7 5336.14,2878.87 ; 5336.14,3044.82 5391.46,3044.82 5363.8,2989.5 5336.14,3044.82 ; 5336.14,3127.79 5349.97,3127.79 5349.97,3113.96 5377.63,3113.96 5377.63,3127.79 5391.46,3127.79 5391.46,3155.45 5377.63,3155.45 5377.63,3169.28 5349.97,3169.28 5349.97,3155.45 5336.14,3155.45 5336.14,3127.79
  lines w12: 5286,2703.25 8518.76,2703.25 ; 5286,3325.54 8518.76,3325.54 ; 5624.17,2578.79 5624.17,3450 ; 5956.28,2578.79 5956.28,3450 ; 6593.29,2578.79 6593.29,3450 ; 6852.64,2578.79 6852.64,3450 ; 7228.06,2578.79 7228.06,3450 ; 7951.91,2578.79 7951.91,3450 ; 5286,2578.79 8518.76,2578.79 8518.76,3450 5286,3450 5286,2578.79
  text "Symbol" at 5360.68,3362.88 h72
  text "Quantity" at 5661.51,3362.88 h72
  text "Finished Hole Size" at 5993.62,3362.88 h72
  text "Plated" at 6630.62,3362.88 h72
  text "Hole Type" at 6889.98,3362.88 h72
  text "Drill Layer Pair" at 7265.4,3362.88 h72
  text "Hole Tolerance" at 7989.25,3362.88 h72
  text "10" at 5661.51,3238.42 h60
  text "10.00mil (0.254mm)" at 5993.62,3238.42 h60
  text "PTH" at 6630.62,3238.42 h60
  text "Round" at 6889.98,3238.42 h60
  text "Top Layer - Bottom Layer" at 7265.4,3238.42 h60
  text "5" at 5661.51,3113.96 h60
  text "25.00mil (0.635mm)" at 5993.62,3113.96 h60
  text "PTH" at 6630.62,3113.96 h60
  text "Round" at 6889.98,3113.96 h60
  text "Top Layer - Bottom Layer" at 7265.4,3113.96 h60
  text "10" at 5661.51,2989.5 h60
  text "40.00mil (1.016mm)" at 5993.62,2989.5 h60
  text "PTH" at 6630.62,2989.5 h60
  text "Round" at 6889.98,2989.5 h60
  text "Top Layer - Bottom Layer" at 7265.4,2989.5 h60
  text "40" at 5661.51,2865.04 h60
  text "45.28mil (1.150mm)" at 5993.62,2865.04 h60
  text "PTH" at 6630.62,2865.04 h60
  text "Round" at 6889.98,2865.04 h60
  text "Top Layer - Bottom Layer" at 7265.4,2865.04 h60
  text "4" at 5661.51,2740.59 h60
  text "98.43mil (2.500mm)" at 5993.62,2740.59 h60
  text "PTH" at 6630.62,2740.59 h60
  text "Round" at 6889.98,2740.59 h60
  text "Top Layer - Bottom Layer" at 7265.4,2740.59 h60
  text "69 Total" at 5661.51,2616.13 h60
  text ".Layer_Name" at 577,-858.49 h60
M17 Embedded Cavity:
  text ".Layer_Name" at 577,-858.49 h60
M18 Embedded Assembly:
  text ".Layer_Name" at 577,-858.49 h60
M19 Embedded Keepout:
  text ".Layer_Name" at 577,-858.49 h60

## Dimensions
0,0 to 2050,0 on M2 Board Dimensions
0,0 to 0,1500 on M2 Board Dimensions
0,-400 to 1000,-400 on M2 Board Dimensions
